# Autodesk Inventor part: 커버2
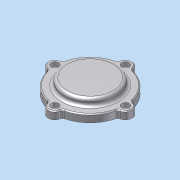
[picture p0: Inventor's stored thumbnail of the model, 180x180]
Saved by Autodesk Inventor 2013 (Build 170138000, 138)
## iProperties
Company: 한국ATC센터
Created: 2015-03
Part Number: 커버2
Document SubType Name: Modeling
Designer: KYOUNG IL JANG
Density: 1 g/cm^3
Material: 일반
Author: KYOUNG IL JANG
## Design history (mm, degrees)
sketch "스케치1"
  geometry: C1 r 1.621 at (0, 6.75) reference; C2 r 1.621 at (-37, -30.25) reference; C3 r 1.621 at (0, -67.25) reference; C4 r 1.621 at (37, -30.25) reference; C5 r 10 at (0, -30.25) reference; C6 r 12 at (0, -30.25); C7 r 24.5 at (0, -30.25) reference; A1 r 3 centre (-38.77, -20.408) between (-38.239, -23.361) and (-35.862, -21.146) reference; A2 r 7 centre (-37, -30.25) between (-38.239, -23.361) and (-38.239, -37.139) reference; A3 r 3 centre (-38.77, -40.092) between (-35.862, -39.354) and (-38.239, -37.139) reference; A4 r 37 centre (0, -30.25) between (-35.862, -39.354) and (-9.104, -66.113) reference; A5 r 3 centre (-9.842, -69.02) between (-6.889, -68.489) and (-9.104, -66.113) reference; A6 r 7 centre (0, -67.25) between (-6.889, -68.489) and (6.889, -68.489) reference; A7 r 3 centre (9.842, -69.02) between (9.104, -66.112) and (6.889, -68.489) reference; A8 r 37 centre (0, -30.25) between (9.104, -66.112) and (35.863, -39.354) reference; A9 r 3 centre (38.77, -40.092) between (38.239, -37.139) and (35.863, -39.354) reference; A10 r 7 centre (37, -30.25) between (38.239, -37.139) and (38.239, -23.361) reference; A11 r 3 centre (38.77, -20.408) between (35.863, -21.146) and (38.239, -23.361) reference; A12 r 37 centre (0, -30.25) between (35.863, -21.146) and (9.104, 5.612) reference; A13 r 3 centre (9.842, 8.52) between (6.889, 7.989) and (9.104, 5.612) reference; A14 r 7 centre (0, 6.75) between (6.889, 7.989) and (-6.889, 7.989) reference; A15 r 3 centre (-9.842, 8.52) between (-9.104, 5.612) and (-6.889, 7.989) reference; A16 r 37 centre (0, -30.25) between (-9.104, 5.612) and (-35.862, -21.146) reference; 1 further point
  constraints: 1 centre point, 1 coincident
  dimensions: "d2" = 2 radial gap between concentric circles of C6 C5
extrude "돌출1" new body sketch "스케치1" distance "d0" = 8; taper "d1" = 0 deg
sketch "스케치2"
  geometry: C1 r 23.5 at (0, -30.25) reference; C2 r 12 at (0, -30.25) reference; 1 further point
extrude "돌출2" join sketch "스케치2" distance "d4" = 5; taper "d5" = 0 deg
sketch "스케치3"
  geometry: C1 r 23.5 at (0, 0) reference; C2 r 20.5 at (0, 0); 1 further point
  constraints: 1 centre point
  dimensions: "d6" = 3 radial gap between concentric circles of C2 C1
node "작업 평면1"
extrude "돌출3" join sketch "스케치3" stored distance "d7" = 5; taper "d8" = 0 deg
fillet "모깎기1" dims "d9" = 3
sketch "스케치4"
  geometry: C1 r 12 at (0, -30.25) reference; C2 r 27 at (0, -30.25); 1 further point
  constraints: 1 centre point
  dimensions: "d10" = 15 radial gap between concentric circles of C1 C2
extrude "돌출4" join sketch "스케치4" distance "d11" = 7; taper "d12" = 0 deg
fillet "모깎기2" dims "d13" = 3
chamfer "모따기1" distance "d14" = 1; stored, may be unused: second distance "d15" = 2, angle "d16" = 45 deg
node "작업점1"
  node "작업축1"
chamfer "모따기2" distance "d24" = 1; stored, may be unused: second distance "d25" = 2, angle "d26" = 45 deg
hole "구멍6" diameter "d43" = 4.5; stored, may be unused: countersink angle "d47" = 90 deg, drill point angle "d49" = 118 deg; dims "d41" = 10, "d42" = 10, "d44" = 6, "d45" = 8, "d46" = 4.4, "d48" = 8
fillet "모깎기4" dims "d60" = 3
node "솔리드1"
pattern_circular "원형 패턴1" dims angle "d51" = 360 deg
node "참조1"
node "참조2"
